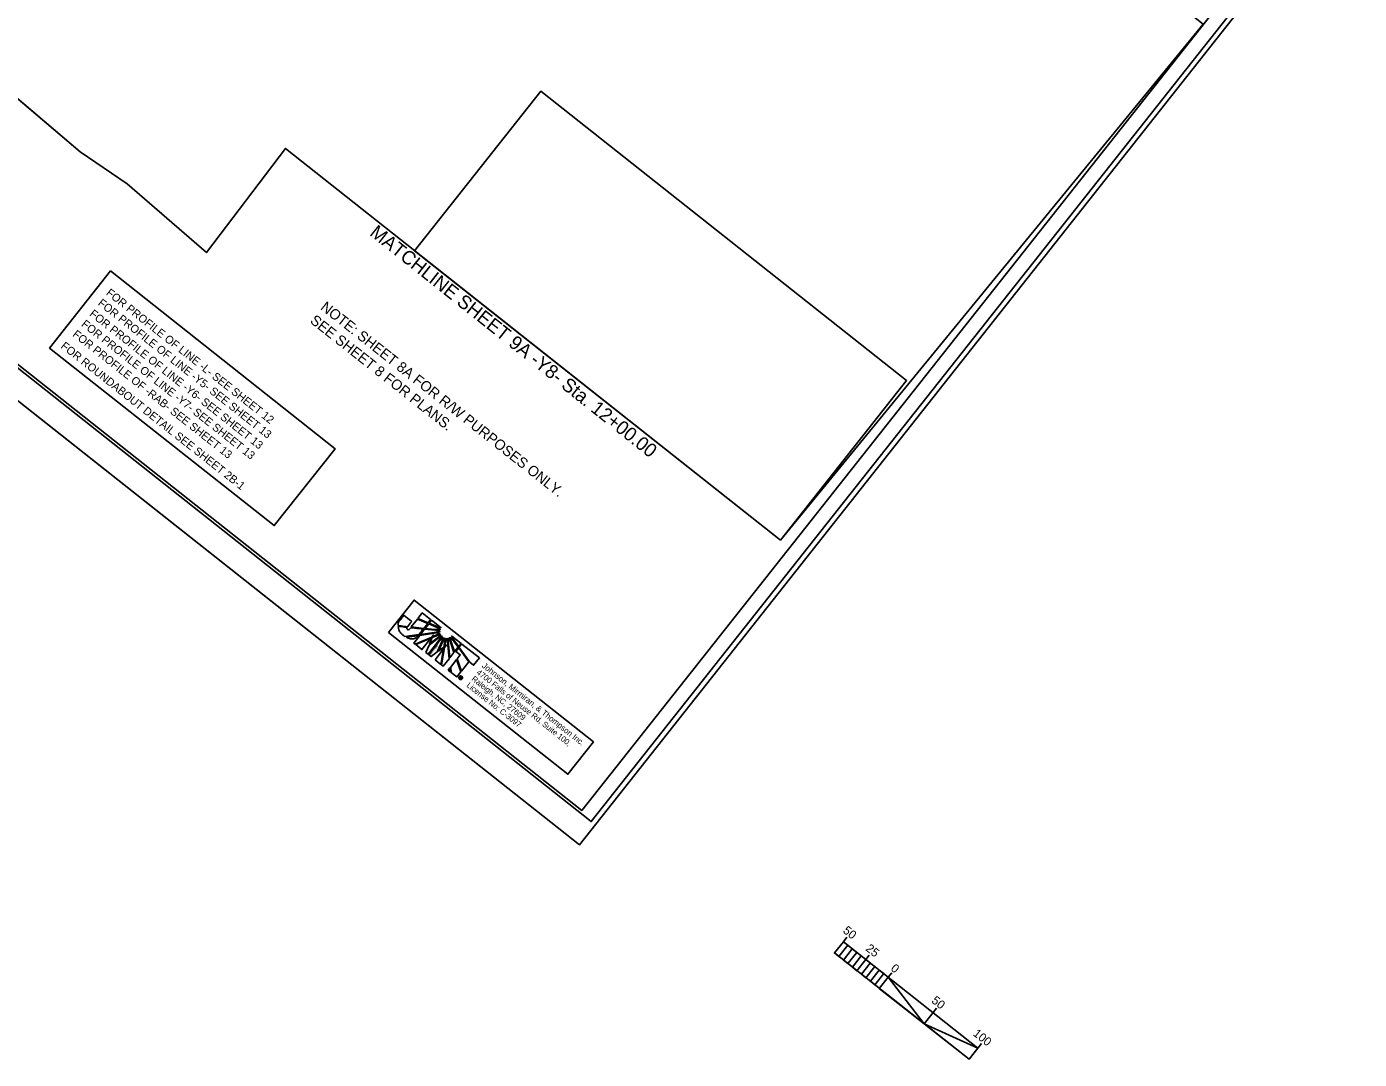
# Model space of a CAD drawing. Extents: x 557005 to 559009, y 505746 to 507841.
# Drawn here: x 557843 to 559009, y 505746 to 506649 of the extents above; entities that cross this region are included whole.
import ezdxf

# ---------------------------------------------------------------- set-up
doc = ezdxf.new("R2010")
doc.units = 0
for name, color, linetype in [('Matchline', 7, 'Continuous'), ('Matchline Text', 7, 'Continuous'), ('Prop Horizontal Alignment Curve and Spiral Data', 7, 'Continuous'), ('Prop Horizontal Alignment Direction Label', 7, 'Continuous'), ('Prop SS Cut Line', 7, 'Continuous'), ('Prop SS Fill Line', 7, 'Continuous'), ('Prop SS Transition Line', 7, 'Continuous'), ('Scratch_Level_5', 7, 'Continuous'), ('Scratch_Level_9', 7, 'Continuous'), ('Sheet Title CELL', 7, 'Continuous')]:
    doc.layers.add(name, color=color, linetype=linetype)

msp = doc.modelspace()

# ---------------------------------------------------------------- linework, layer by layer
at = {"layer": 'Matchline'}
for p, q in [((557889.7, 506539.4), (557425.5, 506933.6)), ((558069.2, 506542.3), (558000.1, 506451.2)), ((558069.1, 506542.3), (558502.2, 506199.9)), ((558285.6, 506371.1), (558289.5, 506368)), ((558188.9, 506136.2), (558185, 506131.3)), ((558196.2, 506130.4), (558188.9, 506136.2)), ((558184.6, 506130.7), (558179.2, 506123.9)), ((558179.2, 506123.9), (558190.2, 506122.7)), ((558193.6, 506127), (558184.6, 506130.7)), ((558185, 506131.3), (558194, 506127.5)), ((558190.9, 506122), (558187.2, 506117.4)), ((558190.2, 506122.7), (558193.6, 506127)), ((558200.4, 506121), (558190.9, 506122)), ((558194.5, 506126.6), (558191.4, 506122.6)), ((558191.4, 506122.6), (558199.6, 506121.7)), ((558194, 506127.5), (558196.2, 506130.4)), ((558202, 506123.4), (558194.5, 506126.6)), ((558197, 506129.8), (558194.9, 506127.2)), ((558194.9, 506127.2), (558202.4, 506124)), ((558205.3, 506123.3), (558197, 506129.8)), ((558199.6, 506121.7), (558204.6, 506121.8)), ((558204.3, 506120.2), (558200.4, 506121)), ((558201.3, 506119.3), (558204.3, 506120.2)), ((558204.6, 506121.8), (558202, 506123.4)), ((558202.4, 506124), (558205.3, 506123.3)), ((558186.6, 506116.6), (558181.4, 506109.9)), ((558181.4, 506109.9), (558182.6, 506109)), ((558182.6, 506109), (558197.1, 506115.1)), ((558196.3, 506114), (558183.1, 506108.5)), ((558183.1, 506108.5), (558188.6, 506104.2)), ((558201.3, 506118.7), (558186.6, 506116.6)), ((558187.2, 506117.4), (558201.3, 506119.3)), ((558188.6, 506104.2), (558196.3, 506114)), ((558194, 506100), (558201.7, 506109.8)), ((558202.2, 506109.4), (558194.5, 506099.6)), ((558203.1, 506114.3), (558194.8, 506108)), ((558195.3, 506109.2), (558203, 506115.1)), ((558197.6, 506114.6), (558195.3, 506109.2)), ((558197.1, 506115.1), (558198.7, 506117)), ((558202.1, 506116.4), (558197.6, 506114.6)), ((558198.7, 506117), (558198, 506115.4)), ((558198, 506115.4), (558201.7, 506117)), ((558204.5, 506118.6), (558201.3, 506118.7)), ((558201.7, 506117), (558204.5, 506118.6)), ((558201.7, 506109.8), (558206, 506115.9)), ((558202, 506102.1), (558206.3, 506111.8)), ((558205, 506117.2), (558202.1, 506116.4)), ((558207.2, 506114.9), (558202.2, 506109.4)), ((558203, 506115.1), (558205, 506117.2)), ((558206, 506115.9), (558203.1, 506114.3)), ((558207, 506111.8), (558203.1, 506102.9)), ((558206.3, 506111.8), (558207.2, 506114.9)), ((558208.6, 506114.3), (558207, 506111.8)), ((558207.8, 506106.4), (558208.6, 506111.3)), ((558209.2, 506111.1), (558208.5, 506106.9)), ((558208.6, 506111.3), (558208.6, 506114.3)), ((558210.2, 506114.2), (558209.2, 506111.1)), ((558210.9, 506111.1), (558210.2, 506114.2)), ((558212.3, 506096.2), (558210.9, 506111.1)), ((558211.7, 506114.4), (558211.6, 506111.2)), ((558211.6, 506111.2), (558212.9, 506097)), ((558213.5, 506110.7), (558211.7, 506114.4)), ((558213.3, 506115), (558214.4, 506110)), ((558215.3, 506112.9), (558213.3, 506115)), ((558216.6, 506101.7), (558213.5, 506110.7)), ((558214.4, 506110), (558217.1, 506102.4)), ((558222.8, 506109.4), (558214.7, 506115.9)), ((558214.7, 506115.9), (558216, 506113.3)), ((558220.2, 506106.2), (558215.3, 506112.9)), ((558216, 506113.3), (558220.7, 506106.8)), ((558220.7, 506106.8), (558222.8, 506109.4)), ((558223.4, 506109), (558221.1, 506106.2)), ((558238.8, 506096.8), (558223.4, 506109)), ((558194.8, 506108), (558192, 506101.6)), ((558192, 506101.6), (558194, 506100)), ((558194.5, 506099.6), (558196.5, 506098)), ((558196.5, 506098), (558202, 506102.1)), ((558207.5, 506104.9), (558200, 506095.3)), ((558203.1, 506102.9), (558207.8, 506106.4)), ((558205.2, 506091.2), (558207.5, 506104.9)), ((558208.3, 506105.9), (558205.8, 506090.7)), ((558210, 506108.1), (558208.3, 506105.9)), ((558208.5, 506106.9), (558210, 506108.1)), ((558212.9, 506097), (558216.6, 506101.7)), ((558217.1, 506102.4), (558220.2, 506106.2)), ((558220.7, 506105.6), (558218.3, 506102.6)), ((558218.3, 506102.6), (558222.1, 506099.7)), ((558222.1, 506099.7), (558219.3, 506096.1)), ((558220.7, 506105.6), (558220.7, 506105.6)), ((558229.5, 506093.4), (558220.7, 506105.6)), ((558221.1, 506106.2), (558221.1, 506106.1)), ((558221.1, 506106.1), (558230.5, 506093.1)), ((558233.8, 506090.5), (558238.8, 506096.8)), ((558200, 506095.3), (558205.2, 506091.2)), ((558205.8, 506090.7), (558207.1, 506089.6)), ((558207.1, 506089.6), (558212.3, 506096.2)), ((558213.1, 506088.2), (558211.5, 506086.2)), ((558211.5, 506086.2), (558213.4, 506084.7)), ((558213.4, 506084.7), (558213.1, 506088.2)), ((558218.9, 506095.5), (558213.7, 506088.9)), ((558213.7, 506088.9), (558214.1, 506084.1)), ((558222.7, 506084.7), (558218.9, 506095.5)), ((558219.3, 506096.1), (558223.1, 506085.3)), ((558223.1, 506085.3), (558229.5, 506093.4)), ((558230.5, 506093.1), (558233.8, 506090.5)), ((558214.1, 506084.1), (558219.1, 506080.2)), ((558219.1, 506080.2), (558222.7, 506084.7)), ((558221.7, 506078.5), (558221.5, 506078.3)), ((558221.5, 506078.3), (558221.7, 506078.5)), ((558221.5, 506078.3), (558221.5, 506078.3)), ((558221.6, 506079.3), (558222.5, 506080.4)), ((558221.8, 506079.1), (558221.6, 506079.3)), ((558221.7, 506078.5), (558221.7, 506078.5)), ((558222.2, 506079.6), (558221.8, 506079.1)), ((558222.4, 506079.4), (558222.2, 506079.6)), ((558222.6, 506080), (558222.3, 506079.8)), ((558222.3, 506079.8), (558222.5, 506079.6)), ((558222.5, 506079.6), (558222.4, 506079.4)), ((558222.4, 506079.4), (558222.5, 506079.6)), ((558222.4, 506079.4), (558222.4, 506079.4)), ((558222.5, 506080.4), (558222.9, 506080.1)), ((558222.5, 506079.6), (558222.6, 506079.6)), ((558222.8, 506079.9), (558222.6, 506080)), ((558222.9, 506080.1), (558222.8, 506079.9)), ((558222.8, 506079.9), (558222.9, 506080.1)), ((558222.8, 506079.8), (558222.8, 506079.9)), ((558222.9, 506080.1), (558223, 506080)), ((558223.4, 506080.8), (558223.3, 506080.5)), ((558223.3, 506080.5), (558223.4, 506080.8))]:
    msp.add_line(p, q, dxfattribs=at)
msp.add_lwpolyline([(558159.3, 506119.2), (558316.2, 505995.1), (558338.6, 506023.4), (558181.7, 506147.5)], close=True, dxfattribs=at)
for points in [[(558185, 506131.3), (558194, 506127.5), (558196.2, 506130.4), (558188.9, 506136.2), (558185, 506131.3)], [(558179.2, 506123.9), (558190.2, 506122.7), (558193.6, 506127), (558184.6, 506130.7), (558179.2, 506123.9)], [(558190.9, 506122), (558187.2, 506117.4), (558201.3, 506119.3), (558204.3, 506120.2), (558200.4, 506121), (558190.9, 506122)], [(558194.5, 506126.6), (558191.4, 506122.6), (558199.6, 506121.7), (558204.6, 506121.8), (558202, 506123.4), (558194.5, 506126.6)], [(558202.4, 506124), (558205.3, 506123.3), (558197, 506129.8), (558194.9, 506127.2), (558202.4, 506124)], [(558204.5, 506118.6), (558201.3, 506118.7), (558186.6, 506116.6), (558181.4, 506109.9), (558182.6, 506109), (558197.1, 506115.1), (558198.7, 506117), (558198, 506115.4), (558201.7, 506117), (558204.5, 506118.6)], [(558183.1, 506108.5), (558188.6, 506104.2), (558196.3, 506114), (558183.1, 506108.5)], [(558203.1, 506114.3), (558194.8, 506108), (558192, 506101.6), (558194, 506100), (558201.7, 506109.8), (558206, 506115.9), (558203.1, 506114.3)], [(558207.2, 506114.9), (558202.2, 506109.4), (558194.5, 506099.6), (558196.5, 506098), (558202, 506102.1), (558206.3, 506111.8), (558207.2, 506114.9)], [(558205, 506117.2), (558202.1, 506116.4), (558197.6, 506114.6), (558195.3, 506109.2), (558203, 506115.1), (558205, 506117.2)], [(558208.6, 506114.3), (558207, 506111.8), (558203.1, 506102.9), (558207.8, 506106.4), (558208.6, 506111.3), (558208.6, 506114.3)], [(558210.2, 506114.2), (558209.2, 506111.1), (558208.5, 506106.9), (558210, 506108.1), (558208.3, 506105.9), (558205.8, 506090.7), (558207.1, 506089.6), (558212.3, 506096.2), (558210.9, 506111.1), (558210.2, 506114.2)], [(558211.7, 506114.4), (558211.6, 506111.2), (558212.9, 506097), (558216.6, 506101.7), (558213.5, 506110.7), (558211.7, 506114.4)], [(558213.3, 506115), (558214.4, 506110), (558217.1, 506102.4), (558220.2, 506106.2), (558215.3, 506112.9), (558213.3, 506115)], [(558216, 506113.3), (558220.7, 506106.8), (558222.8, 506109.4), (558214.7, 506115.9), (558216, 506113.3)], [(558238.8, 506096.8), (558223.4, 506109), (558221.1, 506106.2), (558221.1, 506106.1), (558230.5, 506093.1), (558233.8, 506090.5), (558238.8, 506096.8)], [(558200, 506095.3), (558205.2, 506091.2), (558207.5, 506104.9), (558200, 506095.3)], [(558220.7, 506105.6), (558220.7, 506105.6), (558218.3, 506102.6), (558222.1, 506099.7), (558219.3, 506096.1), (558223.1, 506085.3), (558229.5, 506093.4), (558220.7, 506105.6)], [(558211.5, 506086.2), (558211.5, 506086.2), (558213.4, 506084.7), (558213.1, 506088.2), (558211.5, 506086.2)], [(558218.9, 506095.5), (558213.7, 506088.9), (558214.1, 506084.1), (558219.1, 506080.2), (558222.7, 506084.7), (558218.9, 506095.5), (558218.9, 506095.5)], [(558222.7, 506078.8), (558222.7, 506078.8), (558222.7, 506078.7), (558222.6, 506078.7), (558222.6, 506078.5), (558222.3, 506078.7)]]:
    msp.add_lwpolyline(points, dxfattribs=at)
for points, degree in [([(558179.6, 506128.7), (558179.6, 506128.7), (558172.8, 506134.1), (558172.8, 506134.1), (558172.8, 506134.1), (558169.4, 506129.8), (558169.4, 506129.8), (558169.4, 506129.8), (558169, 506129.4), (558169, 506129.4), (558168, 506128), (558167.6, 506126.6), (558167.7, 506125.1), (558167.7, 506125.1), (558175.9, 506124.1), (558176, 506124.2), (558176, 506124.2), (558179.6, 506128.7), (558179.6, 506128.7)], 3), ([(558175.8, 506121.7), (558175.4, 506122.1), (558175.2, 506122.6), (558175.7, 506123.6), (558175.7, 506123.6), (558167.8, 506124.5), (558167.8, 506124.5), (558168.1, 506121.5), (558169.9, 506118.4), (558172.1, 506116.7), (558172.6, 506116.2), (558173.1, 506115.9), (558173.8, 506115.6), (558173.8, 506115.6), (558185.8, 506117.2), (558185.8, 506117.2), (558185.8, 506117.2), (558189.7, 506122.1), (558189.7, 506122.1), (558189.7, 506122.1), (558178.7, 506123.3), (558178.7, 506123.3), (558177.2, 506121.4), (558176.4, 506121.3), (558175.8, 506121.7)], 3), ([(558175.8, 506121.7), (558175.4, 506122.1), (558175.2, 506122.6), (558175.7, 506123.6), (558175.7, 506123.6), (558167.8, 506124.5), (558167.8, 506124.5), (558168.1, 506121.5), (558169.9, 506118.4), (558172.1, 506116.7), (558172.6, 506116.2), (558173.1, 506115.9), (558173.8, 506115.6), (558173.8, 506115.6), (558185.8, 506117.2), (558185.8, 506117.2), (558185.8, 506117.2), (558189.7, 506122.1), (558189.7, 506122.1), (558189.7, 506122.1), (558178.7, 506123.3), (558178.7, 506123.3), (558177.2, 506121.4), (558176.4, 506121.3), (558175.8, 506121.7)], 3), ([(558185.2, 506116.4), (558185.2, 506116.4), (558174.8, 506115), (558174.8, 506115), (558178.2, 506113.5), (558182.4, 506113.1), (558185.2, 506116.4)], 3), ([(558221.5, 506078.3), (558221.2, 506078.5), (558221, 506078.9), (558220.9, 506079.3), (558220.8, 506079.8), (558221, 506080.2), (558221.2, 506080.5), (558221.5, 506080.9), (558221.9, 506081.1), (558222.3, 506081.1), (558222.7, 506081.1), (558223.1, 506081), (558223.4, 506080.8)], 3), ([(558223.3, 506080.5), (558223, 506080.7), (558222.7, 506080.8), (558222.3, 506080.8), (558222, 506080.8), (558221.7, 506080.6), (558221.5, 506080.3), (558221.3, 506080), (558221.2, 506079.7), (558221.2, 506079.4), (558221.3, 506079), (558221.4, 506078.7), (558221.7, 506078.5)], 3), ([(558223.7, 506078.5), (558223.5, 506078.2), (558223.1, 506078), (558222.7, 506077.9), (558222.2, 506077.9), (558221.9, 506078), (558221.5, 506078.3)], 3), ([(558221.7, 506078.5), (558222, 506078.3), (558222.3, 506078.2), (558222.6, 506078.2), (558223, 506078.3), (558223.3, 506078.5), (558223.5, 506078.7), (558223.7, 506079), (558223.8, 506079.3), (558223.8, 506079.7), (558223.7, 506080), (558223.5, 506080.3), (558223.3, 506080.5)], 3), ([(558222.3, 506078.7), (558222.4, 506078.8), (558222.4, 506078.9), (558222.4, 506079), (558222.5, 506079.1), (558222.6, 506079.1), (558222.6, 506079.2)], 3), ([(558222.6, 506079.2), (558222.5, 506079.2), (558222.5, 506079.3), (558222.4, 506079.4)], 2), ([(558222.6, 506079.6), (558222.7, 506079.5), (558222.8, 506079.5), (558222.9, 506079.5), (558223, 506079.6), (558222.9, 506079.7), (558222.8, 506079.8)], 3), ([(558222.8, 506079.2), (558222.9, 506079.1), (558222.8, 506079), (558222.7, 506078.8)], 2), ([(558223, 506080), (558223.3, 506079.8), (558223.3, 506079.6), (558223.2, 506079.4), (558223.1, 506079.3), (558223, 506079.2), (558222.8, 506079.2)], 3), ([(558223.4, 506080.8), (558223.8, 506080.5), (558224, 506080.1), (558224.1, 506079.7), (558224.1, 506079.3), (558224, 506078.9), (558223.7, 506078.5)], 3)]:
    msp.add_open_spline(points, degree=degree, dxfattribs=at)
at = {"layer": 'Prop Horizontal Alignment Curve and Spiral Data'}
msp.add_lwpolyline([(557916.1, 506435.2), (557862.8, 506367.8), (558059.4, 506212.5), (558112.6, 506279.8), (557916.1, 506435.2)], dxfattribs=at)
at = {"layer": 'Prop Horizontal Alignment Direction Label'}
msp.add_lwpolyline([(559008.5, 506796.2), (557687.6, 507840.7), (557005.3, 506977.8), (558326.3, 505933.3)], close=True, dxfattribs=at)
at = {"layer": 'Prop SS Cut Line'}
msp.add_lwpolyline([(558979.7, 506787.1), (557803.1, 507717.5), (557151.8, 506893.8), (558328.4, 505963.5)], close=True, dxfattribs=at)
at = {"layer": 'Prop SS Fill Line'}
msp.add_lwpolyline([(558991.1, 506781.4), (557683.8, 507815), (557029.4, 506987.4), (558336.7, 505953.7)], close=True, dxfattribs=at)
at = {"layer": 'Prop SS Transition Line'}
for p, q in [((558557.2, 505848.7), (558560.3, 505852.6)), ((558576.8, 505833.2), (558579.9, 505837.1)), ((558635.6, 505786.7), (558638.7, 505790.6)), ((558674.9, 505755.7), (558678, 505759.6))]:
    msp.add_line(p, q, dxfattribs=at)
at = {"layer": 'Scratch_Level_5'}
for points in [[(558502.2, 506199.9), (558069.1, 506542.3), (558000.1, 506451.2), (557930.7, 506511.3), (557889.7, 506539.4), (557425.5, 506933.6), (557395.1, 506959.8), (557368.1, 506966.2), (557439.2, 507142.6), (557392.1, 507195.2), (557803.8, 507716.9), (558807.2, 506891.6), (558715.1, 506775.1), (558872, 506651)], [(558502.2, 506199.9), (558069.1, 506542.3), (558000.1, 506451.2), (557930.7, 506511.3), (557889.7, 506539.4), (557425.5, 506933.6), (557395.1, 506959.8), (557474, 506970.7), (557439.2, 507142.6), (557392.1, 507195.2), (557803.8, 507716.9), (558807.2, 506891.6), (558715.1, 506775.1), (558872, 506651)], [(558502.2, 506199.9), (558182.2, 506452.9), (558292.5, 506592.3), (558612.5, 506339.3)]]:
    msp.add_lwpolyline(points, close=True, dxfattribs=at)
at = {"layer": 'Scratch_Level_9'}
msp.add_line((557005.3, 506977.8), (558326.3, 505933.3), dxfattribs=at)
at = {"layer": 'Sheet Title CELL'}
for p, q in [((558557.2, 505848.7), (558560.3, 505852.6)), ((558557.2, 505848.7), (558549.4, 505838.9)), ((558674.8, 505755.7), (558557.2, 505848.7)), ((558549.4, 505838.9), (558667.1, 505745.9)), ((558576.8, 505833.2), (558579.9, 505837.1)), ((558584.6, 505827), (558576.9, 505817.2)), ((558596.4, 505817.7), (558599.5, 505821.6)), ((558635.6, 505786.7), (558627.9, 505776.9)), ((558635.6, 505786.7), (558638.7, 505790.6)), ((558674.8, 505755.7), (558677.9, 505759.6)), ((558667.1, 505745.9), (558674.8, 505755.7))]:
    msp.add_line(p, q, dxfattribs=at)
for points in [[(558557.2, 505848.7), (558561.1, 505845.6), (558553.3, 505835.8), (558549.4, 505838.9)], [(558565, 505842.5), (558568.9, 505839.4), (558561.2, 505829.6), (558557.3, 505832.7)], [(558572.9, 505836.3), (558576.8, 505833.2), (558569, 505823.4), (558565.1, 505826.5)], [(558580.7, 505830.1), (558584.6, 505827), (558576.9, 505817.2), (558573, 505820.3)], [(558588.6, 505823.9), (558592.5, 505820.8), (558584.7, 505811), (558580.8, 505814.1)], [(558596.4, 505817.7), (558627.9, 505776.9), (558588.6, 505807.9)], [(558674.8, 505755.7), (558627.9, 505776.9), (558667.1, 505745.9)]]:
    msp.add_lwpolyline(points, close=True, dxfattribs=at)

# ---------------------------------------------------------------- texts
at = {"layer": 'Matchline'}
for s, height, rotation, p in [('www.jmt.com', 1.241, 231.6667, (558201.9, 506108)), ('4700 Falls of Neuse Rd, Suite 100, ', 4.965, 321.6667, (558235.9, 506083.3)), ('Johnson, Mirmiran, & Thompson Inc.', 5.111, 321.6667, (558240.6, 506089.1)), ('License No: C-3097', 4.965, 321.6667, (558227.1, 506072.1)), ('Raleigh, NC, 27609', 4.965, 321.6667, (558231.5, 506077.7))]:
    msp.add_text(s, height=height, rotation=rotation, dxfattribs=at).set_placement(p)
at = {"layer": 'Matchline Text'}
msp.add_text('MATCHLINE SHEET 9A -Y8- Sta. 12+00.00', height=12, rotation=321.4798, dxfattribs=at).set_placement((558142.1, 506467))
at = {"layer": 'Prop Horizontal Alignment Curve and Spiral Data'}
for s, height, rotation, p in [('FOR PROFILE OF LINE -L- SEE SHEET 12', 7, 321.6834, (557911.7, 506414.9)), ('FOR PROFILE OF LINE -Y6- SEE SHEET 13', 7, 321.6834, (557897.2, 506396.6)), ('FOR PROFILE OF LINE -Y5- SEE SHEET 13', 7, 321.6834, (557904.6, 506406)), ('NOTE: SHEET 8A FOR R/W PURPOSES ONLY.', 9.1, 321.6834, (558099.2, 506402.1)), ('FOR PROFILE OF LINE -Y7- SEE SHEET 13', 7, 321.6834, (557890.1, 506387.6)), ('SEE SHEET 8 FOR PLANS.', 9.1, 321.6834, (558090, 506390.5)), ('FOR PROFILE OF -RAB- SEE SHEET 13', 7, 321.6667, (557882.4, 506378.7)), ('FOR ROUNDABOUT DETAIL SEE SHEET 2B-1', 7, 321.6667, (557872.1, 506368.4))]:
    msp.add_text(s, height=height, rotation=rotation, dxfattribs=at).set_placement(p)
at = {"layer": 'Sheet Title CELL'}
for s, p in [('50', (558556.2, 505857.3)), ('25', (558576.1, 505841.6)), ('0', (558598, 505824.2)), ('50', (558633.7, 505796.1)), ('100', (558670, 505767.3))]:
    msp.add_text(s, height=7.5, rotation=321.6714, dxfattribs=at).set_placement(p)

doc.saveas('drawing.dxf')
